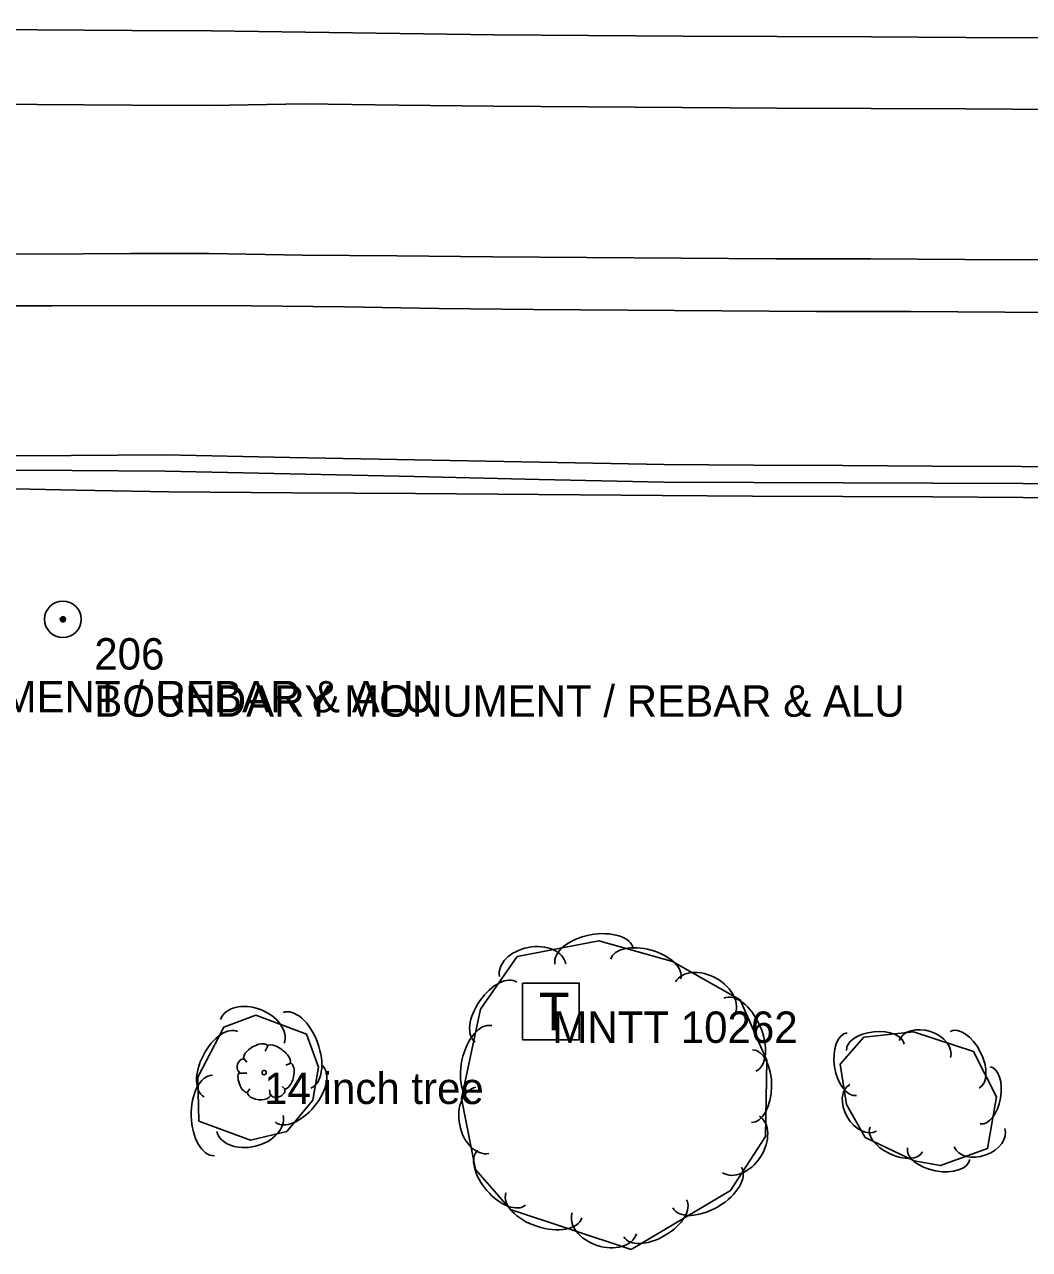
# Model space of a CAD drawing. Extents: x 1802180 to 1804859, y 572524 to 575172.
# Drawn here: x 1804234.6 to 1804394.4, y 573619 to 573813.9 of the extents above; entities that cross this region are included whole.
import ezdxf

# ---------------------------------------------------------------- set-up
doc = ezdxf.new("R2010")
doc.units = 0
for name, color, linetype in [('EX_EDGE_PAVEMENT', 7, 'Continuous'), ('EX_SHOULDER', 7, 'Continuous'), ('S_DITCHLINE', 7, 'Continuous'), ('S_IRON_PIN', 7, 'Continuous'), ('S_IRON_PIN_ANNOT', 7, 'Continuous'), ('S_PAVEMENT_CROWN', 7, 'Continuous'), ('S_TELEPHONE_UTILITIES', 7, 'Continuous'), ('S_TELEPHONE_UTILITIES_ANNOT', 7, 'Continuous'), ('S_TREE', 7, 'Continuous'), ('S_TREE_ANNOT', 7, 'Continuous')]:
    doc.layers.add(name, color=color, linetype=linetype)

msp = doc.modelspace()

# ---------------------------------------------------------------- linework, layer by layer
at = {"layer": 'EX_EDGE_PAVEMENT'}
msp.add_lwpolyline([(1804399.05, 573776.4), (1804384.14, 573776.49), (1804369.14, 573776.56), (1804354.14, 573776.61), (1804339.04, 573776.7), (1804324.04, 573776.8), (1804309.04, 573776.92), (1804293.8, 573777.08), (1804278.8, 573777.19), (1804263.9, 573777.41), (1804251.44, 573777.45), (1804236.44, 573777.33), (1804221.51, 573777.41), (1804206.51, 573777.45), (1804191.51, 573777.48), (1804176.37, 573777.57), (1804161.37, 573777.66), (1804146.36, 573777.77), (1804131.36, 573777.84), (1804116.36, 573777.97), (1804101.74, 573778.07), (1804086.74, 573778.27), (1804071.74, 573778.66)], dxfattribs=at)
at = {"layer": 'EX_SHOULDER'}
for points in [[(1804073.7, 573770.51), (1804088.8, 573770.06), (1804103.85, 573769.76), (1804118.84, 573769.63), (1804133.87, 573769.52), (1804148.84, 573769.47), (1804163.86, 573769.36), (1804178.86, 573769.28), (1804193.89, 573769.19), (1804208.88, 573769.18), (1804223.86, 573769.13), (1804238.97, 573769.08), (1804253.87, 573769.18), (1804270.56, 573769.08)], [(1804270.56, 573769.08), (1804285.47, 573768.95), (1804300.47, 573768.69), (1804315.5, 573768.52), (1804330.52, 573768.41), (1804345.52, 573768.3), (1804360.53, 573768.22), (1804375.55, 573768.19), (1804390.52, 573768.1), (1804405.52, 573768), (1804420.51, 573767.89), (1804435.52, 573767.78), (1804450.52, 573767.69), (1804465.55, 573767.65), (1804480.52, 573767.56), (1804495.37, 573767.21), (1804510.47, 573767.06), (1804525.47, 573766.88), (1804540.38, 573766.7), (1804555.38, 573766.8), (1804570.51, 573767.04), (1804581.48, 573766.76)]]:
    msp.add_lwpolyline(points, dxfattribs=at)
at = {"layer": 'S_DITCHLINE'}
for points in [[(1804137.01, 573744.67), (1804152.07, 573744.76), (1804167.12, 573744.86), (1804182.18, 573744.95), (1804197.24, 573745.05), (1804212.16, 573745.13), (1804227.07, 573745.22), (1804241.99, 573745.31), (1804256.91, 573745.39), (1804276.77, 573745), (1804296.63, 573744.62), (1804316.49, 573744.23), (1804336.35, 573743.84), (1804350.55, 573743.77), (1804364.75, 573743.69), (1804378.96, 573743.62), (1804393.16, 573743.54), (1804407.86, 573743.4)], [(1804137.74, 573742.83), (1804152.74, 573742.9), (1804167.73, 573742.98), (1804182.73, 573743.05), (1804197.73, 573743.12), (1804212.53, 573743.04), (1804227.34, 573742.96), (1804242.14, 573742.88), (1804256.95, 573742.8), (1804276.78, 573742.36), (1804296.61, 573741.93), (1804316.44, 573741.49), (1804336.27, 573741.06), (1804350.54, 573741), (1804364.81, 573740.94), (1804379.08, 573740.88), (1804393.35, 573740.82), (1804407.98, 573740.78)], [(1804138.01, 573741.22), (1804153.16, 573741.07), (1804168.31, 573740.92), (1804183.47, 573740.77), (1804198.62, 573740.61), (1804213.35, 573740.34), (1804228.09, 573740.07), (1804242.82, 573739.8), (1804257.56, 573739.53), (1804277.17, 573739.37), (1804296.78, 573739.22), (1804316.39, 573739.07), (1804336.01, 573738.92), (1804350.36, 573738.84), (1804364.72, 573738.77), (1804379.08, 573738.69), (1804393.44, 573738.62), (1804407.99, 573738.38)]]:
    msp.add_lwpolyline(points, dxfattribs=at)
at = {"layer": 'S_IRON_PIN'}
for radius in [2.91, 0.411, 0.262, 0.212, 0.145, 0.0822, 0.0581]:
    msp.add_circle((1804240.68, 573719.23), radius, dxfattribs=at)
at = {"layer": 'S_PAVEMENT_CROWN'}
for points in [[(1804399.29, 573811.73), (1804384.29, 573811.82), (1804369.29, 573811.89), (1804354.29, 573811.95), (1804339.29, 573812.03), (1804324.29, 573812.14), (1804309.29, 573812.25), (1804294.29, 573812.43), (1804279.3, 573812.64), (1804264.3, 573812.85), (1804251.65, 573812.92), (1804236.65, 573813.01), (1804221.65, 573813.1), (1804206.65, 573813.16), (1804191.65, 573813.22), (1804176.65, 573813.31), (1804161.66, 573813.43), (1804146.66, 573813.55), (1804131.66, 573813.67), (1804116.66, 573813.79), (1804101.66, 573813.87), (1804086.66, 573813.83), (1804071.66, 573813.8)], [(1804071.68, 573802.44), (1804086.68, 573802.18), (1804101.69, 573801.98), (1804116.56, 573801.85), (1804131.56, 573801.73), (1804146.56, 573801.61), (1804161.56, 573801.49), (1804176.56, 573801.41), (1804191.61, 573801.32), (1804206.61, 573801.29), (1804221.61, 573801.23), (1804236.58, 573801.14), (1804251.58, 573801.05), (1804264.16, 573800.96), (1804279.14, 573801.22), (1804294.14, 573801.02), (1804309.21, 573800.86), (1804324.21, 573800.75), (1804339.21, 573800.66), (1804354.24, 573800.57), (1804369.24, 573800.51), (1804384.24, 573800.44), (1804399.21, 573800.35)]]:
    msp.add_lwpolyline(points, dxfattribs=at)
at = {"layer": 'S_TELEPHONE_UTILITIES'}
msp.add_lwpolyline([(1804313.81, 573652.31), (1804313.81, 573661.31), (1804322.81, 573661.31), (1804322.81, 573652.31)], close=True, dxfattribs=at)
at = {"layer": 'S_TREE'}
for p, q in [((1804273.26, 573651.36), (1804272.87, 573650.51)), ((1804269.46, 573649.35), (1804269.97, 573648.76)), ((1804276.83, 573648.57), (1804276.17, 573648.3)), ((1804268.8, 573647.02), (1804269.93, 573647.02)), ((1804269.97, 573643.84), (1804270.43, 573644.54)), ((1804273.65, 573643.57), (1804273.57, 573644.35)), ((1804276.05, 573644.46), (1804275.59, 573644.89))]:
    msp.add_line(p, q, dxfattribs=at)
for points in [[(1804331.09, 573618.98), (1804311.86, 573625.3), (1804306.32, 573631.71), (1804304.1, 573642.97), (1804307.1, 573657.21), (1804312.95, 573665.57), (1804325.96, 573668.07), (1804337.65, 573664.79), (1804348.43, 573658.68), (1804352.65, 573649.04), (1804352.46, 573636.96), (1804346.87, 573628.34), (1804331.09, 573618.98)], [(1804276.31, 573637.73), (1804270.54, 573636.35), (1804262.33, 573639.39), (1804262.15, 573646.38), (1804266.27, 573654.32), (1804271.36, 573656.24), (1804279.44, 573653.2), (1804281.35, 573647.97), (1804280.44, 573642.73), (1804276.31, 573637.73)], [(1804368.3, 573636.79), (1804365.31, 573642.01), (1804364.33, 573648.44), (1804368.06, 573652.76), (1804375.98, 573653.61), (1804385.52, 573650.45), (1804389.19, 573643.23), (1804387.77, 573635.03), (1804380.27, 573632.3), (1804376.1, 573633.08), (1804368.3, 573636.79)]]:
    msp.add_lwpolyline(points, dxfattribs=at)
msp.add_circle((1804272.7, 573647.11), 0.341, dxfattribs=at)
for centre, major_axis, ratio, start_param, end_param in [((1804325.19, 573665.58), (-6.24, -1.2), 0.55008, 3.141593, 6.283185), ((1804315.4, 573663.41), (-5.27, -1.01), 0.685311, 3.141593, 6.283185), ((1804333.41, 573663.59), (-5.57, 1.56), 0.540699, 3.141593, 6.283185), ((1804342.82, 573658.89), (-4.67, 2.65), 0.685311, 3.141593, 6.283185), ((1804309.58, 573656.75), (-3.32, -4.74), 0.540699, 3.141593, 6.283185), ((1804348.35, 573653.14), (-2.55, 5.82), 0.55008, 3.141593, 6.283185), ((1804270.8, 573653.67), (-5.06, 1.9), 0.685311, 3.141593, 6.283185), ((1804277.9, 573650.66), (-2.2, 6.01), 0.55008, 3.141593, 6.283185), ((1804265.83, 573648.44), (-2.68, -5.18), 0.540699, 3.141593, 6.283185), ((1804307.58, 573648.36), (-1.31, -6.22), 0.55008, 3.141593, 6.283185), ((1804366.18, 573648.46), (0.76, -5), 0.55008, 3.141593, 6.283185), ((1804369.92, 573651.12), (-4.58, -0.49), 0.540699, 3.141593, 6.283185), ((1804377.79, 573650.85), (-4.06, 1.34), 0.685311, 3.141593, 6.283185), ((1804384.13, 573649.16), (-2.29, 4.51), 0.55008, 3.141593, 6.283185), ((1804271.37, 573650.32), (1.86, 1.08), 0.471018, 0, 3.141593), ((1804275.02, 573649.99), (-1.81, 1.36), 0.405113, 3.141593, 6.283186), ((1804350.29, 573644.96), (0.09, 5.79), 0.540699, 3.141593, 6.283185), ((1804269.13, 573648.2), (0.31, 1.03), 0.646762, 0, 3.141593), ((1804278.24, 573643.71), (3.72, 4.5), 0.540699, 3.141593, 6.283185), ((1804276.38, 573646.58), (0.46, 2.04), 0.482994, 3.141593, 6.283185), ((1804387.38, 573643.48), (0.79, 4.54), 0.540699, 3.141593, 6.283185), ((1804264.62, 573640.28), (0.16, -6.4), 0.55008, 3.141593, 6.283185), ((1804269.44, 573645.55), (-0.61, 1.6), 0.420543, 6.283185, 9.424777), ((1804271.9, 573643.77), (-1.83, 0.19), 0.529943, 0, 3.141593), ((1804274.86, 573644.06), (1.09, 0.46), 0.711534, 3.141592, 6.283185), ((1804307.41, 573639.51), (1.04, -5.27), 0.685311, 3.141593, 6.283185), ((1804367.96, 573641.52), (2.12, -3.71), 0.685311, 3.141593, 6.283185), ((1804270.44, 573639), (5.26, 1.26), 0.685311, 3.141593, 6.283185), ((1804348.55, 573635.68), (2.92, 4.5), 0.685311, 3.141593, 6.283185), ((1804373.24, 573636.46), (4.16, -1.98), 0.540699, 3.141593, 6.283185), ((1804386.48, 573636.75), (4.01, 1.46), 0.685311, 3.141593, 6.283185), ((1804310.49, 573630.4), (3.79, -4.38), 0.540699, 3.141593, 6.283185), ((1804379.99, 573634.21), (4.97, -0.93), 0.55008, 3.141593, 6.283185), ((1804343.16, 573628.81), (5.47, 3.24), 0.55008, 3.141593, 6.283185), ((1804317.19, 573625.97), (6.04, -1.99), 0.55008, 3.141593, 6.283185), ((1804334.9, 573623.91), (4.98, 2.95), 0.540699, 3.141593, 6.283185), ((1804326.8, 573623.11), (5.1, -1.68), 0.685311, 3.141593, 6.283185)]:
    msp.add_ellipse(centre, major_axis=major_axis, ratio=ratio, start_param=start_param, end_param=end_param, dxfattribs=at)

# ---------------------------------------------------------------- texts
at = {"layer": 'S_IRON_PIN_ANNOT'}
for s, p in [('206', (1804245.68, 573711.23)), ('BOUNDARY MONUMENT / REBAR & ALU ', (1804170.74, 573704.42)), ('BOUNDARY MONUMENT / REBAR & ALU ', (1804245.68, 573703.73))]:
    msp.add_text(s, height=5, dxfattribs=at).set_placement(p)
at = {"layer": 'S_TELEPHONE_UTILITIES'}
msp.add_text('T', height=6, rotation=360, dxfattribs=at).set_placement((1804316.38, 573653.81))
at = {"layer": 'S_TELEPHONE_UTILITIES_ANNOT'}
msp.add_text('MNTT 10262 ', height=5, dxfattribs=at).set_placement((1804318.54, 573651.83))
at = {"layer": 'S_TREE_ANNOT'}
msp.add_text('14 inch tree', height=5, dxfattribs=at).set_placement((1804272.7, 573642.11))

doc.saveas('drawing.dxf')
